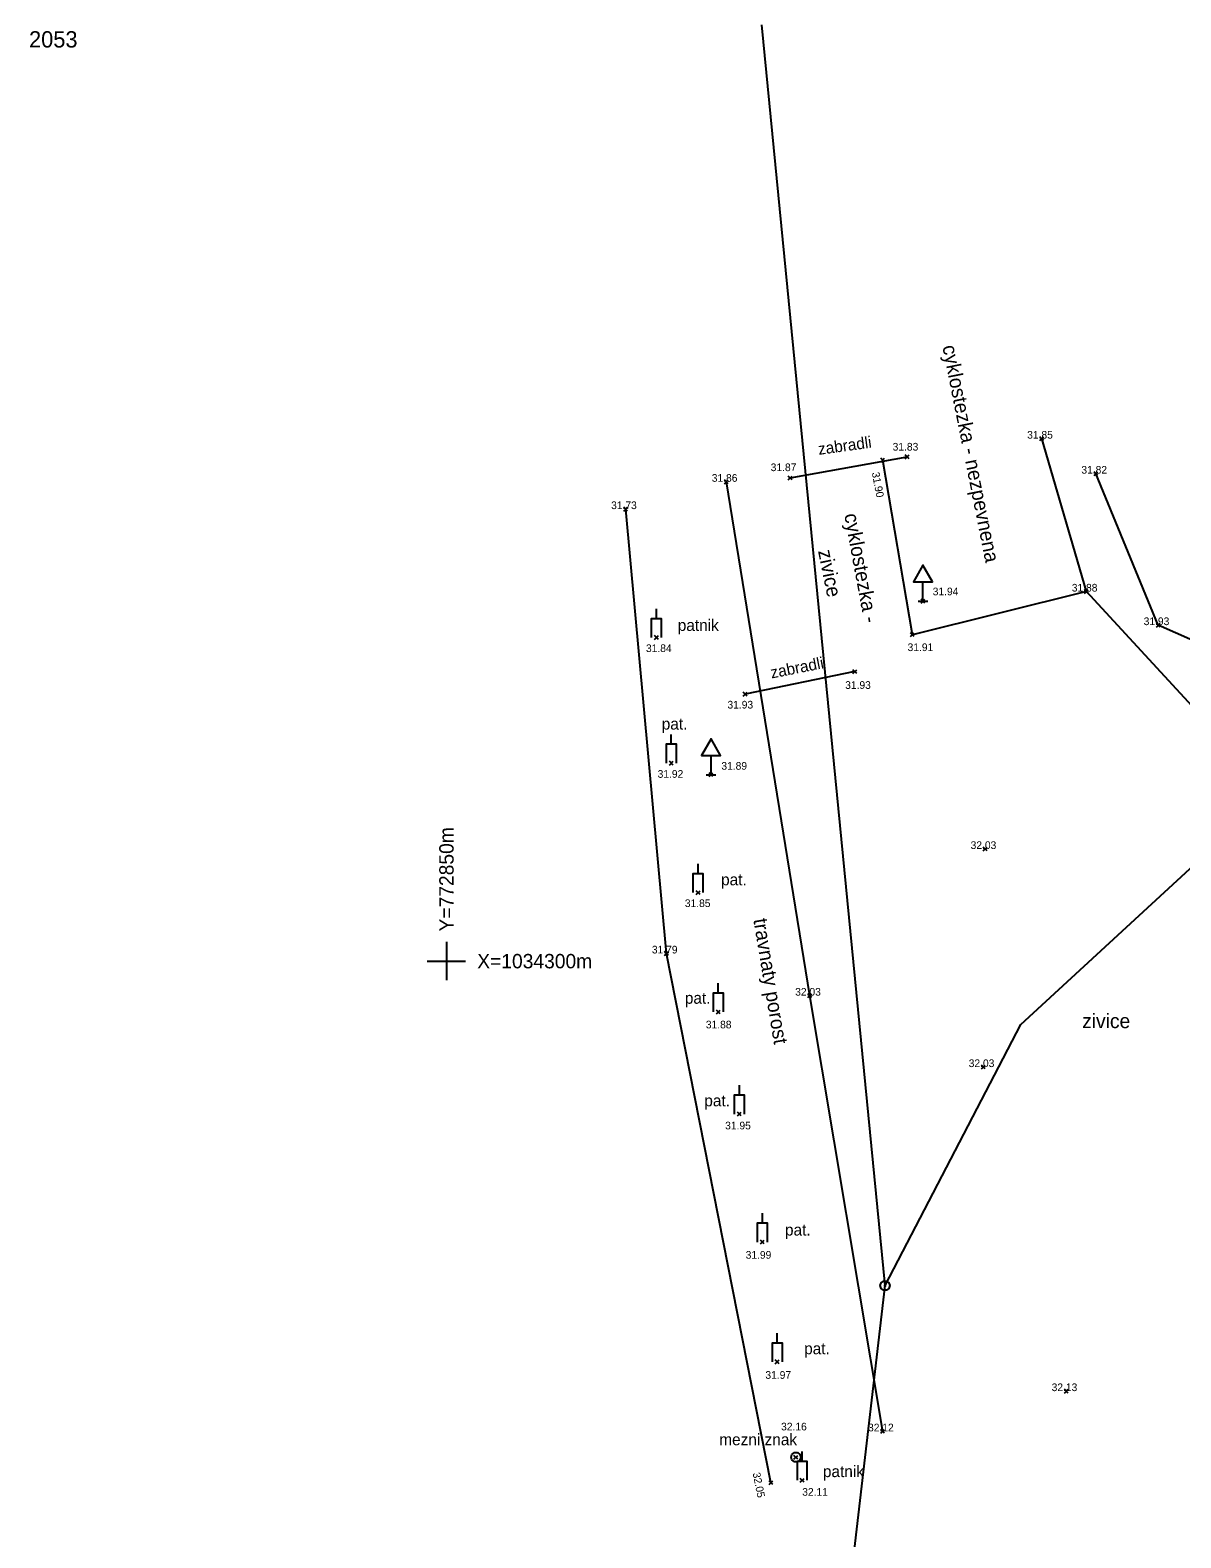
# Model space of a CAD drawing. Extents: x -772865 to -772533, y -1034366 to -1034132.
# Drawn here: x -772858.69 to -772834.68, y -1034312.03 to -1034280.58 of the extents above; entities that cross this region are included whole.
import ezdxf

# ---------------------------------------------------------------- set-up
doc = ezdxf.new("R2010")
doc.units = 0
for name, color, linetype in [('body', 7, 'Continuous'), ('dopravni_znacky', 7, 'Continuous'), ('KM_hranice', 7, 'Continuous'), ('KM_mezni_znaky', 7, 'Continuous'), ('KM_parcelni_cisla', 7, 'Continuous'), ('Level 41', 7, 'Continuous'), ('mistni_popis', 7, 'Continuous'), ('oddeleni_ploch', 7, 'Continuous'), ('ostatni_predmety', 7, 'Continuous'), ('souradnicova_sit', 7, 'Continuous'), ('stromy_kere', 7, 'Continuous'), ('vyskove_koty', 7, 'Continuous')]:
    doc.layers.add(name, color=color, linetype=linetype)

msp = doc.modelspace()

# ---------------------------------------------------------------- linework, layer by layer
at = {"layer": 'body'}
for p, q in [((-772837.54, -1034289.14), (-772837.62, -1034289.06)), ((-772837.62, -1034289.14), (-772837.54, -1034289.06)), ((-772840.86, -1034289.59), (-772840.94, -1034289.51)), ((-772840.94, -1034289.59), (-772840.86, -1034289.51)), ((-772840.35, -1034289.52), (-772840.43, -1034289.44)), ((-772840.43, -1034289.52), (-772840.35, -1034289.44)), ((-772844.12, -1034290.04), (-772844.2, -1034289.96)), ((-772844.2, -1034290.04), (-772844.12, -1034289.96)), ((-772842.79, -1034289.96), (-772842.87, -1034289.88)), ((-772842.87, -1034289.96), (-772842.79, -1034289.88)), ((-772836.41, -1034289.87), (-772836.49, -1034289.79)), ((-772836.49, -1034289.87), (-772836.41, -1034289.79)), ((-772846.22, -1034290.61), (-772846.3, -1034290.53)), ((-772846.3, -1034290.61), (-772846.22, -1034290.53)), ((-772840.02, -1034292.53), (-772840.1, -1034292.45)), ((-772840.1, -1034292.53), (-772840.02, -1034292.45)), ((-772836.61, -1034292.33), (-772836.69, -1034292.25)), ((-772836.69, -1034292.33), (-772836.61, -1034292.25)), ((-772840.24, -1034293.23), (-772840.32, -1034293.15)), ((-772840.32, -1034293.23), (-772840.24, -1034293.15)), ((-772835.11, -1034293.03), (-772835.19, -1034292.95)), ((-772835.19, -1034293.03), (-772835.11, -1034292.95)), ((-772845.58, -1034293.29), (-772845.66, -1034293.21)), ((-772845.66, -1034293.29), (-772845.58, -1034293.21)), ((-772841.44, -1034294), (-772841.52, -1034293.92)), ((-772841.52, -1034294), (-772841.44, -1034293.92)), ((-772843.73, -1034294.47), (-772843.81, -1034294.39)), ((-772843.81, -1034294.47), (-772843.73, -1034294.39)), ((-772845.27, -1034295.91), (-772845.35, -1034295.83)), ((-772845.35, -1034295.91), (-772845.27, -1034295.83)), ((-772844.44, -1034296.15), (-772844.52, -1034296.07)), ((-772844.52, -1034296.15), (-772844.44, -1034296.07)), ((-772838.72, -1034297.7), (-772838.8, -1034297.62)), ((-772838.8, -1034297.7), (-772838.72, -1034297.62)), ((-772844.71, -1034298.61), (-772844.79, -1034298.53)), ((-772844.79, -1034298.61), (-772844.71, -1034298.53)), ((-772845.37, -1034299.88), (-772845.45, -1034299.8)), ((-772845.45, -1034299.88), (-772845.37, -1034299.8)), ((-772842.38, -1034300.76), (-772842.46, -1034300.68)), ((-772842.46, -1034300.76), (-772842.38, -1034300.68)), ((-772844.29, -1034301.1), (-772844.37, -1034301.02)), ((-772844.37, -1034301.1), (-772844.29, -1034301.02)), ((-772838.76, -1034302.25), (-772838.84, -1034302.17)), ((-772838.84, -1034302.25), (-772838.76, -1034302.17)), ((-772843.85, -1034303.23), (-772843.93, -1034303.15)), ((-772843.93, -1034303.23), (-772843.85, -1034303.15)), ((-772843.37, -1034305.9), (-772843.45, -1034305.82)), ((-772843.45, -1034305.9), (-772843.37, -1034305.82)), ((-772843.06, -1034308.4), (-772843.14, -1034308.32)), ((-772843.14, -1034308.4), (-772843.06, -1034308.32)), ((-772837.03, -1034309.01), (-772837.11, -1034308.93)), ((-772837.11, -1034309.01), (-772837.03, -1034308.93)), ((-772840.86, -1034309.85), (-772840.94, -1034309.77)), ((-772840.94, -1034309.85), (-772840.86, -1034309.77)), ((-772842.67, -1034310.39), (-772842.75, -1034310.31)), ((-772842.75, -1034310.39), (-772842.67, -1034310.31)), ((-772843.19, -1034310.92), (-772843.27, -1034310.84)), ((-772843.27, -1034310.92), (-772843.19, -1034310.84)), ((-772842.54, -1034310.87), (-772842.62, -1034310.79)), ((-772842.62, -1034310.87), (-772842.54, -1034310.79))]:
    msp.add_line(p, q, dxfattribs=at)
at = {"layer": 'dopravni_znacky'}
for p, q in [((-772840.16, -1034292.49), (-772839.96, -1034292.49)), ((-772844.58, -1034296.11), (-772844.38, -1034296.11))]:
    msp.add_line(p, q, dxfattribs=at)
for points in [[(-772840.06, -1034292.49), (-772840.06, -1034292.09), (-772839.86, -1034292.09), (-772840.06, -1034291.74), (-772840.26, -1034292.09), (-772840.06, -1034292.09)], [(-772844.48, -1034296.11), (-772844.48, -1034295.71), (-772844.28, -1034295.71), (-772844.48, -1034295.36), (-772844.68, -1034295.71), (-772844.48, -1034295.71)]]:
    msp.add_lwpolyline(points, dxfattribs=at)
at = {"layer": 'KM_hranice'}
for p, q in [((-772840.85, -1034306.77), (-772843.42, -1034280.47)), ((-772838.02, -1034301.32), (-772833.5, -1034297.16)), ((-772840.85, -1034306.77), (-772838.02, -1034301.32)), ((-772841.56, -1034312.87), (-772840.85, -1034306.77))]:
    msp.add_line(p, q, dxfattribs=at)
at = {"layer": 'KM_mezni_znaky'}
msp.add_line((-772840.874, -1034306.77), (-772840.826, -1034306.77), dxfattribs=at)
msp.add_lwpolyline([(-772840.82, -1034306.674), (-772840.77, -1034306.71), (-772840.75, -1034306.768), (-772840.77, -1034306.826), (-772840.82, -1034306.862), (-772840.882, -1034306.862), (-772840.932, -1034306.826), (-772840.952, -1034306.768), (-772840.932, -1034306.71), (-772840.882, -1034306.674)], close=True, dxfattribs=at)
at = {"layer": 'Level 41'}
msp.add_line((-772842.734, -1034310.35), (-772842.686, -1034310.35), dxfattribs=at)
msp.add_lwpolyline([(-772842.68, -1034310.254), (-772842.63, -1034310.29), (-772842.61, -1034310.348), (-772842.63, -1034310.406), (-772842.68, -1034310.442), (-772842.742, -1034310.442), (-772842.792, -1034310.406), (-772842.812, -1034310.348), (-772842.792, -1034310.29), (-772842.742, -1034310.254)], close=True, dxfattribs=at)
at = {"layer": 'oddeleni_ploch'}
msp.add_line((-772836.65, -1034292.29), (-772837.58, -1034289.1), dxfattribs=at)
for points in [[(-772828.52, -1034296.12), (-772832.4, -1034296.9), (-772836.65, -1034292.29), (-772840.28, -1034293.19), (-772840.9, -1034289.55)], [(-772840.9, -1034309.81), (-772842.42, -1034300.72), (-772844.16, -1034290)]]:
    msp.add_lwpolyline(points, dxfattribs=at)
at = {"layer": 'ostatni_predmety'}
for p, q in [((-772842.83, -1034289.92), (-772840.39, -1034289.48)), ((-772845.62, -1034292.85), (-772845.62, -1034292.65)), ((-772841.48, -1034293.96), (-772843.77, -1034294.43)), ((-772845.31, -1034295.47), (-772845.31, -1034295.27)), ((-772844.75, -1034298.17), (-772844.75, -1034297.97)), ((-772844.33, -1034300.66), (-772844.33, -1034300.46)), ((-772843.89, -1034302.79), (-772843.89, -1034302.59)), ((-772843.41, -1034305.46), (-772843.41, -1034305.26)), ((-772843.1, -1034307.96), (-772843.1, -1034307.76)), ((-772842.58, -1034310.43), (-772842.58, -1034310.23))]:
    msp.add_line(p, q, dxfattribs=at)
for points in [[(-772845.72, -1034293.25), (-772845.72, -1034292.85), (-772845.52, -1034292.85), (-772845.52, -1034293.25)], [(-772845.41, -1034295.87), (-772845.41, -1034295.47), (-772845.21, -1034295.47), (-772845.21, -1034295.87)], [(-772844.85, -1034298.57), (-772844.85, -1034298.17), (-772844.65, -1034298.17), (-772844.65, -1034298.57)], [(-772844.43, -1034301.06), (-772844.43, -1034300.66), (-772844.23, -1034300.66), (-772844.23, -1034301.06)], [(-772843.99, -1034303.19), (-772843.99, -1034302.79), (-772843.79, -1034302.79), (-772843.79, -1034303.19)], [(-772843.51, -1034305.86), (-772843.51, -1034305.46), (-772843.31, -1034305.46), (-772843.31, -1034305.86)], [(-772843.2, -1034308.36), (-772843.2, -1034307.96), (-772843, -1034307.96), (-772843, -1034308.36)], [(-772842.68, -1034310.83), (-772842.68, -1034310.43), (-772842.48, -1034310.43), (-772842.48, -1034310.83)]]:
    msp.add_lwpolyline(points, dxfattribs=at)
at = {"layer": 'souradnicova_sit'}
for p, q in [((-772850, -1034299.6), (-772850, -1034300.4)), ((-772850.4, -1034300), (-772849.6, -1034300))]:
    msp.add_line(p, q, dxfattribs=at)
at = {"layer": 'stromy_kere'}
for points in [[(-772830.27, -1034280.7), (-772828.11, -1034289.32), (-772832.98, -1034293.95), (-772835.15, -1034292.99), (-772836.45, -1034289.83)], [(-772843.23, -1034310.88), (-772845.41, -1034299.84), (-772846.26, -1034290.57)]]:
    msp.add_lwpolyline(points, dxfattribs=at)

# ---------------------------------------------------------------- texts
at = {"layer": 'KM_parcelni_cisla'}
msp.add_text('2053', height=0.34, dxfattribs=at).set_placement((-772858.708, -1034280.94))
at = {"layer": 'mistni_popis'}
for s, height, rotation, p in [('cyklostezka - nezpevnena', 0.3, 281.265, (-772839.655, -1034287.177)), ('zabradli', 0.24, 7.8495, (-772842.232, -1034289.439)), ('cyklostezka -', 0.3, 280.4628, (-772841.703, -1034290.685)), ('zivice', 0.3, 281.4942, (-772842.25, -1034291.445)), ('zabradli', 0.24, 11.1154, (-772843.217, -1034294.104)), ('travnaty porost', 0.3, 279.4315, (-772843.599, -1034299.133))]:
    msp.add_text(s, height=height, rotation=rotation, dxfattribs=at).set_placement(p)
for s, height, p in [('patnik', 0.24, (-772845.175, -1034293.111)), ('pat.', 0.24, (-772845.509, -1034295.169)), ('pat.', 0.24, (-772844.271, -1034298.418)), ('pat.', 0.24, (-772845.027, -1034300.889)), ('zivice', 0.3, (-772836.738, -1034301.398)), ('pat.', 0.24, (-772844.621, -1034303.029)), ('pat.', 0.24, (-772842.938, -1034305.725)), ('pat.', 0.24, (-772842.538, -1034308.201)), ('mezni znak', 0.24, (-772844.309, -1034310.099)), ('patnik', 0.24, (-772842.147, -1034310.764))]:
    msp.add_text(s, height=height, dxfattribs=at).set_placement(p)
at = {"layer": 'souradnicova_sit'}
msp.add_text('Y=772850m', height=0.3, rotation=90.0117, dxfattribs=at).set_placement((-772849.85, -1034299.381))
msp.add_text('X=1034300m', height=0.3, dxfattribs=at).set_placement((-772849.358, -1034300.15))
at = {"layer": 'vyskove_koty'}
for s, p in [('31.85', (-772837.885, -1034289.1)), ('31.83', (-772840.692, -1034289.349)), ('31.87', (-772843.236, -1034289.778)), ('31.82', (-772836.755, -1034289.83)), ('31.86', (-772844.465, -1034290)), ('31.73', (-772846.565, -1034290.57)), ('31.94', (-772839.856, -1034292.368)), ('31.88', (-772836.955, -1034292.29)), ('31.93', (-772835.455, -1034292.99)), ('31.84', (-772845.838, -1034293.552)), ('31.91', (-772840.38, -1034293.532)), ('31.93', (-772841.682, -1034294.32)), ('31.93', (-772844.138, -1034294.73)), ('31.89', (-772844.265, -1034296.007)), ('31.92', (-772845.595, -1034296.175)), ('32.03', (-772839.065, -1034297.66)), ('31.85', (-772845.027, -1034298.872)), ('31.79', (-772845.715, -1034299.84)), ('32.03', (-772842.725, -1034300.72)), ('31.88', (-772844.589, -1034301.403)), ('32.03', (-772839.105, -1034302.21)), ('31.95', (-772844.186, -1034303.51)), ('31.99', (-772843.758, -1034306.208)), ('31.97', (-772843.346, -1034308.713)), ('32.13', (-772837.375, -1034308.97)), ('32.16', (-772843.019, -1034309.79)), ('32.12', (-772841.205, -1034309.81)), ('32.11', (-772842.578, -1034311.153))]:
    msp.add_text(s, height=0.16, dxfattribs=at).set_placement(p)
for s, rotation, p in [('31.90', 280.7493, (-772841.127, -1034289.813)), ('32.05', 281.265, (-772843.614, -1034310.681))]:
    msp.add_text(s, height=0.16, rotation=rotation, dxfattribs=at).set_placement(p)

doc.saveas('drawing.dxf')
